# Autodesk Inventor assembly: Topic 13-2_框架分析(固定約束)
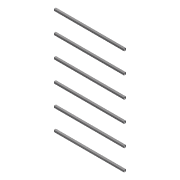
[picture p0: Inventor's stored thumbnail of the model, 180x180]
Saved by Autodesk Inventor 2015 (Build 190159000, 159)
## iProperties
Created: 2020-03
Part Number: Topic 13-2_框架分析(固定約束)
Document SubType Name: Assembly
Designer: 徐冠倫
Mass: 14532.6 g
Surface Area: 12379 cm^2
Volume: 1851.29 cm^3
Density: 7.85 g/cm^3
_SolveAssemblyDoc: Frame Generator Solve Assembly
_Version: 15.0.0
Author: 徐冠倫
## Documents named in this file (3)
- C:\Users\徐冠倫\Desktop\Topic 12-3_框架分析(銷約束)\Topic 12-3_框架分析(銷約束).iam
- C:\Users\徐冠倫\Desktop\Topic 12-3_框架分析(銷約束)\Topic 12-3_框架分析(銷約束).ipt
- C:\Users\徐冠倫\Desktop\Topic 12-3_框架分析(銷約束)\Topic 12-3_框架分析(銷約束)\Frame\Frame0001.iam
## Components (7 placed, 2 different names)
1. Topic 12-3_框架分析(銷約束):1
2. Frame0001:1 [sub-assembly]
3. Frame0001:2 [sub-assembly]
4. Frame0001:3 [sub-assembly]
5. Frame0001:4 [sub-assembly]
6. Frame0001:5 [sub-assembly]
7. Frame0001:6 [sub-assembly]
